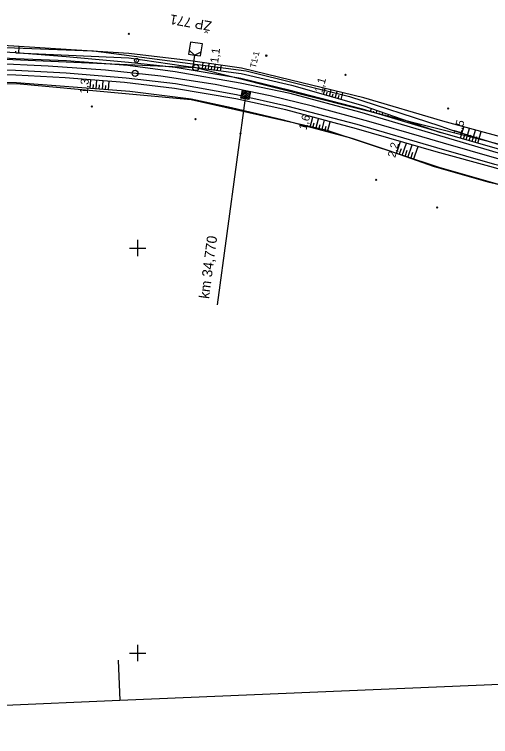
# Model space of a CAD drawing. Extents: x -806456 to -805395, y -1150847 to -1150506.
# Drawn here: x -805630.4 to -805512.9, y -1150820.6 to -1150642.3 of the extents above; entities that cross this region are included whole.
import ezdxf

# ---------------------------------------------------------------- set-up
doc = ezdxf.new("R2010")
doc.units = 0
for name, color, linetype in [('0381KM032-037P - Vrstva 1', 7, 'Continuous'), ('0381KM032-037P - Vrstva 3', 7, 'Continuous'), ('0381KM032-037P - Vrstva 4', 7, 'Continuous'), ('0381KM032-037P - Vrstva 48', 7, 'Continuous'), ('0381KM032-037P - Vrstva 49', 7, 'Continuous'), ('0381KM032-037P - Vrstva 7', 7, 'Continuous'), ('formát', 7, 'Continuous'), ('hran DP - hran DP', 7, 'Continuous'), ('krizky_1000 - Vrstva 1', 7, 'Continuous'), ('vyt_sit - ohrožené', 7, 'Continuous'), ('vyt_sit - polygon', 7, 'Continuous')]:
    doc.layers.add(name, color=color, linetype=linetype)

msp = doc.modelspace()

# ---------------------------------------------------------------- linework, layer by layer
at = {"layer": '0381KM032-037P - Vrstva 1'}
for points in [[(-805607.93, -1150656.05), (-805622.11, -1150655.05), (-805635.9, -1150654.45), (-805647.61, -1150654.06)], [(-805567.32, -1150662.37), (-805580.89, -1150659.62), (-805594.29, -1150657.54), (-805607.93, -1150656.05)], [(-805529.81, -1150672.54), (-805542.91, -1150668.73), (-805556.85, -1150664.92), (-805567.32, -1150662.37)], [(-805499.4, -1150681.08), (-805511.35, -1150677.89), (-805524.48, -1150674.12), (-805529.81, -1150672.54)]]:
    msp.add_lwpolyline(points, dxfattribs=at)
at = {"layer": '0381KM032-037P - Vrstva 3'}
for p, q in [((-805573.17, -1150661.19), (-805580.37, -1150714.04)), ((-805574.52, -1150662.97), (-805572.18, -1150661.37)), ((-805574.42, -1150662.44), (-805572.71, -1150661.27)), ((-805574.32, -1150661.92), (-805573.23, -1150661.17)), ((-805574.23, -1150661.4), (-805573.75, -1150661.08)), ((-805574, -1150663.06), (-805572.28, -1150661.89)), ((-805573.48, -1150663.16), (-805572.38, -1150662.41)), ((-805572.96, -1150663.26), (-805572.48, -1150662.93))]:
    msp.add_line(p, q, dxfattribs=at)
msp.add_lwpolyline([(-805574.15, -1150661), (-805572.18, -1150661.37), (-805572.55, -1150663.34), (-805574.52, -1150662.97)], close=True, dxfattribs=at)
at = {"layer": '0381KM032-037P - Vrstva 4'}
for points in [[(-805485.85, -1150681.76), (-805498.96, -1150678.92), (-805510.6, -1150675.66), (-805525.22, -1150671.48), (-805544.53, -1150665.72), (-805562.31, -1150661.11), (-805574.56, -1150658.15), (-805590.74, -1150655.42), (-805602.22, -1150654.14), (-805617.62, -1150652.74), (-805630.08, -1150651.83), (-805647.65, -1150650.8), (-805688.26, -1150650.5)], [(-805423.97, -1150686.92), (-805425.51, -1150687.49), (-805433.17, -1150688.49), (-805447.58, -1150687.79), (-805460.54, -1150686.52), (-805473.03, -1150684.97), (-805486, -1150682.53), (-805499.06, -1150679.64), (-805510.93, -1150676.58), (-805525.41, -1150672.29), (-805545.14, -1150666.47), (-805562.36, -1150661.85), (-805574.71, -1150659.28), (-805590.7, -1150656.46), (-805602.42, -1150654.96), (-805617.57, -1150653.8), (-805630.08, -1150653.28), (-805647.6, -1150652.35), (-805687.98, -1150651.47)], [(-805425.98, -1150691.47), (-805433.13, -1150691.22), (-805447.47, -1150690.71), (-805460.74, -1150689.57), (-805473.54, -1150687.87), (-805486.2, -1150685.62), (-805499.7, -1150682.42), (-805511.82, -1150679.35), (-805526.11, -1150675.23), (-805545.84, -1150669.48), (-805563.16, -1150664.96), (-805575.57, -1150662.2), (-805590.62, -1150659.46), (-805602.86, -1150658.06), (-805617.64, -1150656.78), (-805630.16, -1150656.16), (-805647.73, -1150655.65), (-805688.15, -1150654.42)], [(-805425.41, -1150692.47), (-805425.98, -1150691.47), (-805433.11, -1150692.35), (-805447.61, -1150691.82), (-805460.9, -1150690.59), (-805473.67, -1150688.98), (-805486.26, -1150686.57), (-805500.08, -1150683.65), (-805512.15, -1150680.12), (-805526.27, -1150676.26), (-805545.98, -1150670.57), (-805563.42, -1150665.87), (-805575.79, -1150663.12), (-805590.93, -1150660.59), (-805603.28, -1150659.09), (-805617.92, -1150657.97), (-805630.11, -1150657.32), (-805646.66, -1150657.1), (-805648.58, -1150657.2), (-805687.42, -1150655.93)]]:
    msp.add_lwpolyline(points, dxfattribs=at)
at = {"layer": '0381KM032-037P - Vrstva 48'}
for p, q in [((-805630.09, -1150651.83), (-805630.06, -1150651.34)), ((-805629.34, -1150651.86), (-805629.27, -1150650.24)), ((-805583.99, -1150655.65), (-805583.8, -1150654.21)), ((-805583.25, -1150655.75), (-805583.15, -1150655.03)), ((-805582.5, -1150655.85), (-805582.31, -1150654.42)), ((-805581.02, -1150656.05), (-805580.83, -1150654.64)), ((-805579.53, -1150656.25), (-805579.34, -1150654.85)), ((-805581.76, -1150655.95), (-805581.66, -1150655.24)), ((-805580.27, -1150656.15), (-805580.18, -1150655.44)), ((-805611.7, -1150660.6), (-805611.54, -1150658.46)), ((-805610.21, -1150660.72), (-805610.04, -1150658.57)), ((-805610.96, -1150660.66), (-805610.87, -1150659.59)), ((-805609.46, -1150660.78), (-805609.38, -1150659.7)), ((-805608.71, -1150660.83), (-805608.55, -1150658.69)), ((-805607.96, -1150660.89), (-805607.88, -1150659.82)), ((-805607.21, -1150660.95), (-805607.05, -1150658.8)), ((-805554.11, -1150662.05), (-805553.7, -1150660.58)), ((-805553.39, -1150662.26), (-805553.18, -1150661.51)), ((-805552.67, -1150662.46), (-805552.24, -1150660.94)), ((-805551.95, -1150662.67), (-805551.73, -1150661.89)), ((-805551.23, -1150662.87), (-805550.78, -1150661.3)), ((-805549.79, -1150663.28), (-805549.32, -1150661.66)), ((-805550.51, -1150663.08), (-805550.28, -1150662.28)), ((-805542.53, -1150666.31), (-805542.3, -1150665.55)), ((-805541.81, -1150666.53), (-805541.7, -1150666.16)), ((-805541.09, -1150666.74), (-805540.88, -1150666.04)), ((-805540.37, -1150666.96), (-805540.27, -1150666.62)), ((-805539.65, -1150667.17), (-805539.46, -1150666.53)), ((-805538.93, -1150667.39), (-805538.84, -1150667.08)), ((-805538.21, -1150667.6), (-805538.04, -1150667.03)), ((-805557.45, -1150670.15), (-805556.79, -1150667.66)), ((-805556.72, -1150670.35), (-805556.39, -1150669.1)), ((-805556, -1150670.54), (-805555.34, -1150668.05)), ((-805554.55, -1150670.93), (-805553.89, -1150668.44)), ((-805553.1, -1150671.31), (-805552.44, -1150668.83)), ((-805555.28, -1150670.73), (-805554.95, -1150669.49)), ((-805553.83, -1150671.12), (-805553.5, -1150669.88)), ((-805520.31, -1150672.89), (-805519.5, -1150670.07)), ((-805518.86, -1150673.3), (-805518.05, -1150670.46)), ((-805517.42, -1150673.71), (-805516.6, -1150670.86)), ((-805519.58, -1150673.09), (-805519.18, -1150671.68)), ((-805518.14, -1150673.5), (-805517.73, -1150672.08)), ((-805516.7, -1150673.92), (-805516.29, -1150672.49)), ((-805515.98, -1150674.12), (-805515.16, -1150671.25)), ((-805536.11, -1150676.64), (-805535.09, -1150673.71)), ((-805534.69, -1150677.13), (-805533.65, -1150674.13)), ((-805533.28, -1150677.62), (-805532.21, -1150674.54)), ((-805535.4, -1150676.88), (-805534.89, -1150675.4)), ((-805533.99, -1150677.38), (-805533.46, -1150675.85)), ((-805532.57, -1150677.87), (-805532.03, -1150676.31)), ((-805531.86, -1150678.11), (-805530.76, -1150674.96))]:
    msp.add_line(p, q, dxfattribs=at)
at = {"layer": '0381KM032-037P - Vrstva 49'}
for p, q in [((-805602.01, -1150646.92), (-805602.36, -1150647.28)), ((-805602.36, -1150646.92), (-805602.01, -1150647.28)), ((-805568.05, -1150652.69), (-805568.41, -1150652.34)), ((-805568.05, -1150652.34), (-805568.41, -1150652.69)), ((-805548.54, -1150657.39), (-805548.89, -1150657.04)), ((-805548.54, -1150657.04), (-805548.89, -1150657.39)), ((-805611.13, -1150664.88), (-805611.48, -1150665.23)), ((-805611.48, -1150664.88), (-805611.12, -1150665.23)), ((-805523.18, -1150665.72), (-805523.53, -1150665.37)), ((-805523.18, -1150665.37), (-805523.53, -1150665.72)), ((-805585.52, -1150668), (-805585.87, -1150668.36)), ((-805585.87, -1150668), (-805585.52, -1150668.36)), ((-805574.41, -1150671.9), (-805574.76, -1150671.55)), ((-805574.41, -1150671.55), (-805574.76, -1150671.9)), ((-805540.92, -1150683.33), (-805541.28, -1150682.98)), ((-805540.92, -1150682.98), (-805541.28, -1150683.33)), ((-805525.86, -1150690.16), (-805526.21, -1150689.81)), ((-805525.86, -1150689.81), (-805526.21, -1150690.16))]:
    msp.add_line(p, q, dxfattribs=at)
for points in [[(-805602.19, -1150651.94), (-805630.54, -1150650.16), (-805647.04, -1150649.14), (-805681.66, -1150649.9), (-805688.26, -1150650.5)], [(-805423.97, -1150686.92), (-805433.1, -1150687.91), (-805447.34, -1150686.91), (-805460.49, -1150686.09), (-805485.85, -1150681.76), (-805498.96, -1150678.92), (-805510.6, -1150675.66), (-805525.22, -1150671.48), (-805544.53, -1150665.72), (-805562.31, -1150661.11), (-805571.99, -1150658.79), (-805574.56, -1150658.15), (-805590.74, -1150655.42), (-805602.22, -1150654.14), (-805617.62, -1150652.74), (-805630.08, -1150651.83), (-805647.65, -1150650.8), (-805688.26, -1150650.5)], [(-805630.08, -1150651.83), (-805602.16, -1150653.02), (-805588.68, -1150655.02)], [(-805424.36, -1150683.57), (-805432.74, -1150683.28), (-805452.35, -1150683.91), (-805462.43, -1150682.34), (-805472.3, -1150680.9), (-805485.84, -1150678.15), (-805509.51, -1150672.79), (-805524.62, -1150668.67), (-805544.15, -1150662.92), (-805562.19, -1150658.51), (-805574.34, -1150655.56), (-805587.56, -1150653.68), (-805602.19, -1150651.94)], [(-805588.68, -1150655.02), (-805574.43, -1150656.93), (-805562.03, -1150659.8), (-805544.41, -1150664.81), (-805525.22, -1150671.48)], [(-805425.41, -1150692.47), (-805425.98, -1150691.47), (-805433.11, -1150692.35), (-805447.61, -1150691.82), (-805460.9, -1150690.59), (-805473.67, -1150688.98), (-805486.26, -1150686.57), (-805500.08, -1150683.65), (-805512.15, -1150680.12), (-805526.27, -1150676.26), (-805545.98, -1150670.57), (-805563.42, -1150665.87), (-805575.79, -1150663.12), (-805590.93, -1150660.59), (-805603.28, -1150659.09), (-805617.92, -1150657.97), (-805630.11, -1150657.32), (-805646.15, -1150657.11), (-805646.27, -1150657.1), (-805646.57, -1150657.13), (-805646.66, -1150657.1), (-805648.58, -1150657.2), (-805687.42, -1150655.93)], [(-805428.8, -1150698.61), (-805426.99, -1150695.45), (-805434.79, -1150695.76), (-805452.59, -1150694.8), (-805474.79, -1150691.73), (-805486.9, -1150690.07), (-805513.13, -1150683.83), (-805526.69, -1150679.91), (-805538.18, -1150675.92), (-805547.05, -1150672.92), (-805563.97, -1150668.42), (-805576.87, -1150665.35), (-805586.81, -1150663.24), (-805590.73, -1150662.74), (-805601.92, -1150661.35), (-805629.88, -1150659.22), (-805648.74, -1150658.99), (-805687.58, -1150660.02)]]:
    msp.add_lwpolyline(points, dxfattribs=at)
at = {"layer": '0381KM032-037P - Vrstva 7'}
for p, q in [((-805585.93, -1150652.33), (-805586.39, -1150655.29)), ((-805600.32, -1150653.66), (-805600.22, -1150653.66)), ((-805586.89, -1150655.21), (-805585.9, -1150655.37))]:
    msp.add_line(p, q, dxfattribs=at)
for points in [[(-805585.93, -1150652.33), (-805584.45, -1150652.56), (-805583.99, -1150649.59), (-805586.96, -1150649.13), (-805587.42, -1150652.1), (-805585.93, -1150652.33)], [(-805587.26, -1150651.11), (-805585.93, -1150652.33), (-805584.3, -1150651.57)]]:
    msp.add_lwpolyline(points, dxfattribs=at)
for centre, radius in [((-805600.27, -1150653.66), 0.5), ((-805600.62, -1150656.85), 0.75)]:
    msp.add_circle(centre, radius, dxfattribs=at)
at = {"layer": 'formát'}
for p, q in [((-805604.84, -1150801.71), (-805604.42, -1150811.7)), ((-805394.61, -1150802.8), (-805604.42, -1150811.7)), ((-805604.42, -1150811.7), (-805814.23, -1150820.61))]:
    msp.add_line(p, q, dxfattribs=at)
at = {"layer": 'hran DP - hran DP'}
for p, q in [((-805645.21, -1150649.93), (-805611.34, -1150651.29)), ((-805611.34, -1150651.29), (-805610.86, -1150651.29)), ((-805610.86, -1150651.29), (-805573.24, -1150656.2)), ((-805573.24, -1150656.2), (-805547.66, -1150662.54)), ((-805629.87, -1150659.45), (-805660.75, -1150659.79)), ((-805613.77, -1150660.92), (-805629.87, -1150659.45)), ((-805586.79, -1150663.39), (-805613.77, -1150660.92)), ((-805553.22, -1150670.95), (-805586.79, -1150663.39)), ((-805547.66, -1150662.54), (-805525.39, -1150669.85)), ((-805525.6, -1150680.1), (-805553.22, -1150670.95)), ((-805525.39, -1150669.85), (-805522.57, -1150670.78)), ((-805522.57, -1150670.78), (-805505.56, -1150676.07)), ((-805492.06, -1150689.65), (-805525.6, -1150680.1))]:
    msp.add_line(p, q, dxfattribs=at)
at = {"layer": 'krizky_1000 - Vrstva 1'}
for points in [[(-805600, -1150698), (-805600, -1150702)], [(-805602, -1150700), (-805598, -1150700)], [(-805600, -1150798), (-805600, -1150802)], [(-805602, -1150800), (-805598, -1150800)]]:
    msp.add_lwpolyline(points, dxfattribs=at)
at = {"layer": 'vyt_sit - ohrožené'}
msp.add_line((-805585.69, -1150655.42), (-805585.58, -1150655.42), dxfattribs=at)
msp.add_circle((-805585.64, -1150655.42), 0.756, dxfattribs=at)
at = {"layer": 'vyt_sit - polygon'}
for p, q in [((-805759.38, -1150647.88), (-805585.64, -1150655.42)), ((-805585.64, -1150655.42), (-805426.99, -1150695.45))]:
    msp.add_line(p, q, dxfattribs=at)

# ---------------------------------------------------------------- texts
at = {"layer": '0381KM032-037P - Vrstva 3'}
for s, height, rotation, p in [('T1-1', 1.5, 76.1469, (-805570.87, -1150655.63)), ('km 34,770', 2.5, 82.5204, (-805582.38, -1150712.62))]:
    msp.add_text(s, height=height, rotation=rotation, dxfattribs=at).set_placement(p)
at = {"layer": '0381KM032-037P - Vrstva 48'}
for s, rotation, p in [('1,1', 82.3827, (-805580.14, -1150654.4)), ('1,3', 85.6488, (-805612.3, -1150661.94)), ('1,1', 74.1019, (-805554.47, -1150661.8)), ('1,6', 75.1245, (-805558.33, -1150670.98)), ('1,5', 74.0489, (-805520.28, -1150672.25)), ('2,2', 75.6961, (-805536.41, -1150677.81))]:
    msp.add_text(s, height=2, rotation=rotation, dxfattribs=at).set_placement(p)
at = {"layer": 'vyt_sit - ohrožené'}
msp.add_text('ŽP 771', height=2.4, rotation=170, dxfattribs=at).set_placement((-805581.59, -1150644.08))

doc.saveas('drawing.dxf')
